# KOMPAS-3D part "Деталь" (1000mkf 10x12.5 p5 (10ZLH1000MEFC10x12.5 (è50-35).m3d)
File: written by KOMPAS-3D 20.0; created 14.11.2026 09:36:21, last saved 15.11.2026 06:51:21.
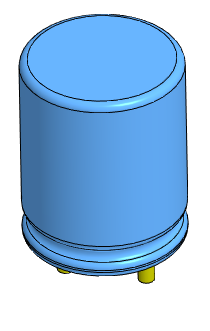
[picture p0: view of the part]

Document properties: Полное имя файла: D:\myProjects\Progect_esp32\box_compas\прочее\1000mkf 10x112_5 p5.m3d

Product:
- Part/product: Деталь
    Масса: 0.0076211

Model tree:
1. Эскиз:1
2. Элемент вращения:1
     Угол 1 = 360
3. Скругление:1  (with: Элемент вращения:1)
     Радиус = 0.5
4. Эскиз:2  (with: Элемент вращения:1, Скругление:1)
5. Элемент выдавливания:1
     Расстояние 1 = 3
